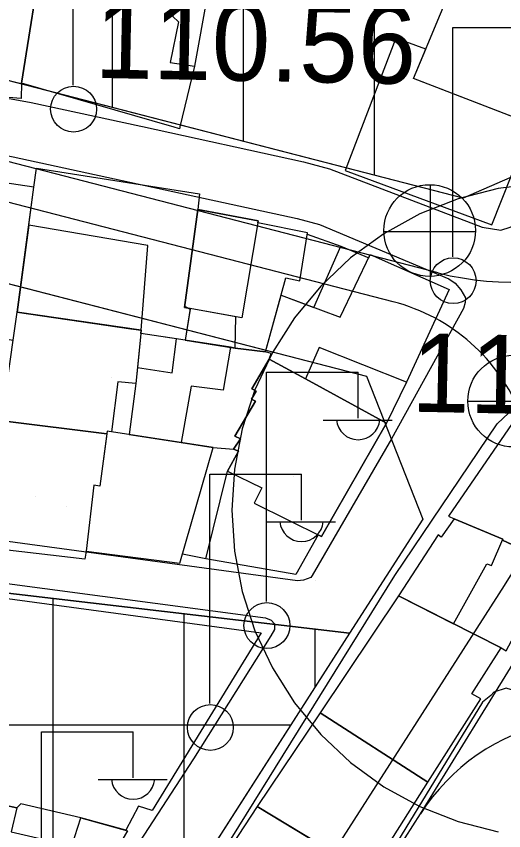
# Model space of a CAD drawing. Extents: x 417997 to 421451, y 4451742 to 4455216.
# Drawn here: x 419408.8 to 419446, y 4452992.5 to 4453054.6 of the extents above; entities that cross this region are included whole.
import ezdxf

# ---------------------------------------------------------------- set-up
doc = ezdxf.new("R2010")
doc.units = 0
for name, color, linetype in [('ADA', 7, 'Continuous'), ('ADAKENARI', 7, 'Continuous'), ('B_Mesken', 7, 'Continuous'), ('B_Teras', 7, 'Continuous'), ('Default', 7, 'Continuous'), ('KALDIRIM', 7, 'Continuous'), ('KD_KAV_25', 7, 'Continuous'), ('PL_AYA_PARK_DINLENME', 7, 'Continuous'), ('PL_K_TALI_IS_MRK', 7, 'Continuous'), ('PL_KON_MEV_350', 7, 'Continuous'), ('S_Elektrik_Diregi', 7, 'Continuous'), ('S_Rogar_Kapagi', 7, 'Continuous'), ('S_Rogar_Kapagi_Buski', 7, 'Continuous'), ('Sinir_Duvar_tek_tarafa_ait', 7, 'Continuous'), ('TR_ORTAYOGUNKONUT', 7, 'Continuous'), ('TR_PARKALANI', 7, 'Continuous'), ('TR_TALIISMERK', 7, 'Continuous'), ('Y_Kot_Noktasi', 7, 'Continuous'), ('Y_Yol_Kotu', 7, 'Continuous'), ('Yol_Sose', 7, 'Continuous')]:
    doc.layers.add(name, color=color, linetype=linetype)

# ---------------------------------------------------------------- blocks, each defined once
blk = doc.blocks.new('POINT_DISPLAY')
at = {"layer": 'Default'}
blk.add_line((0, 0), (0, 0), dxfattribs=at)

msp = doc.modelspace()

# ---------------------------------------------------------------- linework, layer by layer
at = {"layer": 'ADA'}
msp.add_line((419355.52, 4453016.764), (419434.233, 4453007.553), dxfattribs=at)
msp.add_line((419355.52, 4453016.764), (419434.233, 4453007.553), dxfattribs=at)
at = {"layer": 'ADAKENARI'}
for p, q in [((419442.899, 4453040.766), (419384.91, 4453055.74)), ((419442.899, 4453040.766), (419384.91, 4453055.74)), ((419457.346, 4453047.058), (419442.899, 4453040.766)), ((419457.346, 4453047.058), (419442.899, 4453040.766)), ((419381.159, 4453041.217), (419435.524, 4453027.178)), ((419381.159, 4453041.217), (419435.524, 4453027.178)), ((419435.524, 4453027.178), (419439.812, 4453016.259)), ((419435.524, 4453027.178), (419439.812, 4453016.259)), ((419439.812, 4453016.259), (419434.233, 4453007.553)), ((419439.812, 4453016.259), (419434.233, 4453007.553)), ((419434.233, 4453007.553), (419385.322, 4452931.225)), ((419434.233, 4453007.553), (419385.322, 4452931.225))]:
    msp.add_line(p, q, dxfattribs=at)
at = {"layer": 'B_Mesken'}
for points in [[(419420.666, 4453046.222), (419409.186, 4453049.529), (419410.842, 4453059.952), (419411.033, 4453061.438), (419421.12, 4453059.541), (419421.636, 4453062.642), (419424.233, 4453062.289), (419423.393, 4453056.331), (419421.129, 4453056.77), (419420.742, 4453054.629), (419421.174, 4453054.212), (419420.522, 4453051.125), (419422.377, 4453050.845), (419421.271, 4453046.216), (419421.265, 4453046.19), (419421.234, 4453046.059), (419420.758, 4453046.196)], [(419402.672, 4453060.235), (419410.741, 4453059.319), (419409.186, 4453049.529), (419409.149, 4453048.363), (419401.142, 4453049.015), (419401.09, 4453049.314)], [(419449.396, 4453045.919), (419439.117, 4453049.894), (419443.231, 4453059.792), (419455.025, 4453054.467), (419455.109, 4453053.862), (419451.734, 4453045.894), (419451.722, 4453045.865), (419451.414, 4453045.138), (419449.472, 4453045.889)], [(419439.117, 4453049.894), (419440.047, 4453052.132), (419437.763, 4453052.968), (419433.899, 4453042.869), (419445.103, 4453038.723), (419448.143, 4453046.403)], [(419401.551, 4453042.864), (419400.277, 4453032.838), (419400.042, 4453031.307), (419408.543, 4453029.914), (419408.843, 4453032.044), (419410.132, 4453041.595)], [(419408.843, 4453032.044), (419409.742, 4453038.702), (419410.132, 4453041.595), (419410.315, 4453043.054), (419422.759, 4453041.102), (419422.654, 4453039.904), (419421.637, 4453032.52), (419422.057, 4453032.29), (419421.686, 4453029.929), (419418.294, 4453030.428), (419418.319, 4453030.675), (419408.843, 4453032.044), (419409.742, 4453038.702)], [(419431.014, 4453038.126), (419427.219, 4453038.879), (419427.243, 4453039.021), (419422.654, 4453039.904), (419421.622, 4453032.414), (419422.064, 4453032.334), (419421.686, 4453029.929), (419425.496, 4453029.315), (419427.818, 4453029.023), (419429.358, 4453034.667), (419430.435, 4453034.442)], [(419433.569, 4453037.098), (419435.694, 4453036.204), (419435.814, 4453036.454), (419441.841, 4453033.784), (419438.568, 4453026.717), (419437.043, 4453023.586), (419430.855, 4453026.965), (419428.099, 4453028.47), (419428.249, 4453028.9), (419427.818, 4453029.023), (419429.002, 4453033.361), (419431.505, 4453032.42)], [(419408.04, 4453026.336), (419408.843, 4453032.044), (419417.525, 4453030.773), (419418.319, 4453030.675), (419417.905, 4453026.603), (419416.53, 4453026.727), (419416.062, 4453022.919), (419415.724, 4453022.972), (419415.696, 4453022.76), (419407.741, 4453023.767)], [(419417.905, 4453026.603), (419417.398, 4453022.714), (419421.36, 4453022.103), (419423.81, 4453021.726), (419425.375, 4453021.602), (419425.89, 4453022.374), (419425.461, 4453022.578), (419427.044, 4453025.271), (419426.75, 4453025.416), (419427.096, 4453026.03), (419426.775, 4453026.203), (419428.099, 4453028.47), (419428.249, 4453028.9), (419427.818, 4453029.023), (419425.496, 4453029.315), (419425.149, 4453029.371), (419421.686, 4453029.929), (419421.02, 4453030.027), (419418.294, 4453030.428), (419418.029, 4453027.821)], [(419431.821, 4453015.048), (419430.118, 4453012.031), (419423.244, 4453013.218), (419424.912, 4453019.905), (419425.751, 4453021.454), (419425.375, 4453021.602), (419425.89, 4453022.374), (419425.461, 4453022.578), (419427.044, 4453025.271), (419426.75, 4453025.416), (419427.096, 4453026.03), (419426.775, 4453026.203), (419428.099, 4453028.47), (419430.855, 4453026.965), (419437.043, 4453023.586), (419432.087, 4453014.916)], [(419407.741, 4453023.767), (419415.696, 4453022.76), (419415.172, 4453018.773), (419414.703, 4453018.843), (419414.114, 4453013.812), (419414.007, 4453013.204), (419406.563, 4453014.05), (419406.7, 4453014.834)], [(419449.452, 4453013.005), (419453.702, 4453020.945), (419447.42, 4453023.91), (419447.16, 4453023.409), (419446.642, 4453023.566), (419441.778, 4453016.491), (419442.203, 4453016.287), (419445.931, 4453014.725), (419445.895, 4453014.64)], [(419415.724, 4453022.972), (419415.172, 4453018.773), (419414.703, 4453018.843), (419414.114, 4453013.812), (419421.263, 4453012.88), (419423.81, 4453021.726)], [(419445.808, 4453006.43), (419446.187, 4453006.205), (419449.753, 4453012.867), (419445.895, 4453014.64), (419445.931, 4453014.725), (419442.203, 4453016.287), (419441.23, 4453014.872), (419441.006, 4453015.062), (419437.974, 4453010.4)], [(419407.736, 4453010.236), (419427.49, 4453007.565), (419419.151, 4452994.016), (419418.111, 4452994.347), (419417.152, 4452992.492), (419413.708, 4452993.452), (419409.131, 4452994.518), (419408.813, 4452994.207), (419406.912, 4452994.625), (419407.667, 4452997.33), (419405.031, 4452997.855), (419405.429, 4452999.7), (419405.672, 4452999.668)], [(419431.981, 4453001.461), (419440.208, 4452996.16), (419444.239, 4453002.528), (419443.566, 4453002.91), (419445.808, 4453006.43), (419437.974, 4453010.4)], [(419431.981, 4453001.461), (419427.178, 4452994.322), (419435.749, 4452989.116), (419440.208, 4452996.16)], [(419405.788, 4452993.345), (419406.106, 4452994.803), (419408.813, 4452994.207), (419408.39, 4452992.368), (419413.023, 4452991.301), (419413.708, 4452993.452), (419417.282, 4452992.456), (419410.401, 4452980.854), (419403.442, 4452982.29), (419403.523, 4452982.486), (419403.934, 4452984.794), (419404.258, 4452984.736)], [(419427.178, 4452994.322), (419422.828, 4452987.667), (419431.329, 4452982.651), (419435.468, 4452989.286)]]:
    msp.add_lwpolyline(points, close=True, dxfattribs=at)
at = {"layer": 'B_Teras'}
for points in [[(419409.742, 4453038.702), (419410.132, 4453041.595), (419410.315, 4453043.054), (419422.759, 4453041.102), (419422.654, 4453039.904), (419421.637, 4453032.52), (419422.057, 4453032.29), (419421.686, 4453029.929), (419418.294, 4453030.428), (419418.319, 4453030.675), (419418.829, 4453037.143)], [(419421.622, 4453032.414), (419422.654, 4453039.904), (419427.243, 4453039.021), (419425.996, 4453031.619)], [(419429.002, 4453033.361), (419433.512, 4453031.665), (419435.814, 4453036.454), (419441.841, 4453033.784), (419438.568, 4453026.717), (419431.914, 4453029.353), (419430.855, 4453026.965), (419428.099, 4453028.47), (419428.249, 4453028.9), (419427.818, 4453029.023)], [(419422.064, 4453032.334), (419421.686, 4453029.929), (419425.496, 4453029.315), (419425.551, 4453031.7)], [(419418.294, 4453030.428), (419418.029, 4453027.821), (419420.68, 4453027.436), (419421.02, 4453030.027)], [(419425.149, 4453029.371), (419424.567, 4453026.099), (419422.129, 4453026.41), (419421.36, 4453022.103), (419423.81, 4453021.726), (419425.375, 4453021.602), (419425.89, 4453022.374), (419425.461, 4453022.578), (419427.044, 4453025.271), (419426.75, 4453025.416), (419427.096, 4453026.03), (419426.775, 4453026.203), (419428.099, 4453028.47), (419428.249, 4453028.9), (419427.818, 4453029.023), (419425.496, 4453029.315)], [(419428.099, 4453028.47), (419426.775, 4453026.203), (419427.096, 4453026.03), (419426.75, 4453025.416), (419427.044, 4453025.271), (419425.461, 4453022.578), (419425.89, 4453022.374), (419425.375, 4453021.602), (419425.751, 4453021.454), (419424.912, 4453019.905), (419427.534, 4453018.651), (419426.953, 4453017.475), (419432.087, 4453014.916), (419437.043, 4453023.586)], [(419442.176, 4453008.27), (419444.715, 4453012.827), (419445.078, 4453012.723), (419445.931, 4453014.725), (419442.203, 4453016.287), (419441.23, 4453014.872), (419441.006, 4453015.062), (419437.974, 4453010.4)]]:
    msp.add_lwpolyline(points, close=True, dxfattribs=at)
at = {"layer": 'KALDIRIM'}
for p, q in [((419441.005, 4453035.058), (419383.409, 4453049.931)), ((419441.005, 4453035.058), (419383.409, 4453049.931)), ((419437.561, 4453032.849), (419382.659, 4453047.026)), ((419437.561, 4453032.849), (419382.659, 4453047.026)), ((419439.64, 4452993.75), (419460.258, 4453027.246)), ((419439.64, 4452993.75), (419460.258, 4453027.246)), ((419392.057, 4452926.909), (419446.065, 4453011.19)), ((419392.057, 4452926.909), (419446.065, 4453011.19)), ((419395.425, 4452924.751), (419439.64, 4452993.75)), ((419395.425, 4452924.751), (419439.64, 4452993.75))]:
    msp.add_line(p, q, dxfattribs=at)
for centre, radius, start, end in [((419446.493, 4453056.311), 21.95, 255.52117, 331.54687), ((419446.493, 4453056.311), 21.95, 255.52117, 331.54687), ((419433.97, 4453018.94), 14.365, 327.34809, 75.52117), ((419433.97, 4453018.94), 14.365, 327.34809, 75.52117), ((419453.09, 4452985.131), 15.974, 57.20227, 147.34809), ((419453.09, 4452985.131), 15.974, 57.20227, 147.34809)]:
    msp.add_arc(centre, radius, start, end, dxfattribs=at)
at = {"layer": 'KD_KAV_25'}
for p, q in [((419448.677, 4453041.883), (419445.562, 4453041.489)), ((419448.677, 4453041.883), (419445.562, 4453041.489)), ((419445.562, 4453041.489), (419442.521, 4453040.709)), ((419445.562, 4453041.489), (419442.521, 4453040.709)), ((419442.521, 4453040.709), (419439.602, 4453039.553)), ((419442.521, 4453040.709), (419439.602, 4453039.553)), ((419439.602, 4453039.553), (419436.851, 4453038.04)), ((419439.602, 4453039.553), (419436.851, 4453038.04)), ((419436.851, 4453038.04), (419434.311, 4453036.195)), ((419436.851, 4453038.04), (419434.311, 4453036.195)), ((419434.311, 4453036.195), (419432.022, 4453034.046)), ((419434.311, 4453036.195), (419432.022, 4453034.046)), ((419432.022, 4453034.046), (419430.021, 4453031.627)), ((419432.022, 4453034.046), (419430.021, 4453031.627)), ((419430.021, 4453031.627), (419428.339, 4453028.976)), ((419430.021, 4453031.627), (419428.339, 4453028.976)), ((419428.339, 4453028.976), (419427.002, 4453026.135)), ((419428.339, 4453028.976), (419427.002, 4453026.135)), ((419427.002, 4453026.135), (419426.032, 4453023.149)), ((419427.002, 4453026.135), (419426.032, 4453023.149)), ((419426.032, 4453023.149), (419425.443, 4453020.066)), ((419426.032, 4453023.149), (419425.443, 4453020.066)), ((419425.443, 4453020.066), (419425.246, 4453016.932)), ((419425.443, 4453020.066), (419425.246, 4453016.932)), ((419425.246, 4453016.932), (419425.443, 4453013.799)), ((419425.246, 4453016.932), (419425.443, 4453013.799)), ((419425.443, 4453013.799), (419426.032, 4453010.715)), ((419425.443, 4453013.799), (419426.032, 4453010.715)), ((419426.032, 4453010.715), (419427.002, 4453007.729)), ((419426.032, 4453010.715), (419427.002, 4453007.729)), ((419427.002, 4453007.729), (419428.339, 4453004.888)), ((419427.002, 4453007.729), (419428.339, 4453004.888)), ((419428.339, 4453004.888), (419430.021, 4453002.238)), ((419428.339, 4453004.888), (419430.021, 4453002.238)), ((419430.021, 4453002.238), (419432.022, 4452999.819)), ((419430.021, 4453002.238), (419432.022, 4452999.819)), ((419432.022, 4452999.819), (419434.311, 4452997.669)), ((419432.022, 4452999.819), (419434.311, 4452997.669)), ((419434.311, 4452997.669), (419436.851, 4452995.824)), ((419434.311, 4452997.669), (419436.851, 4452995.824)), ((419436.851, 4452995.824), (419439.602, 4452994.312)), ((419436.851, 4452995.824), (419439.602, 4452994.312)), ((419439.602, 4452994.312), (419442.521, 4452993.156)), ((419439.602, 4452994.312), (419442.521, 4452993.156)), ((419442.521, 4452993.156), (419445.562, 4452992.375)), ((419442.521, 4452993.156), (419445.562, 4452992.375))]:
    msp.add_line(p, q, dxfattribs=at)
at = {"layer": 'PL_AYA_PARK_DINLENME'}
msp.add_lwpolyline([(419435.524, 4453027.178), (419439.812, 4453016.259), (419434.233, 4453007.553), (419355.52, 4453016.764), (419351.123, 4453030.039), (419370.073, 4453034.551), (419381.159, 4453041.217)], close=True, dxfattribs=at)
msp.add_lwpolyline([(419435.524, 4453027.178), (419439.812, 4453016.259), (419434.233, 4453007.553), (419355.52, 4453016.764), (419351.123, 4453030.039), (419370.073, 4453034.551), (419381.159, 4453041.217)], close=True, dxfattribs=at)
at = {"layer": 'PL_K_TALI_IS_MRK'}
msp.add_lwpolyline([(419351.123, 4453030.039), (419355.52, 4453016.764), (419434.233, 4453007.553), (419385.322, 4452931.225), (419381.957, 4452925.774), (419378.777, 4452920.212), (419375.787, 4452914.546), (419372.99, 4452908.783), (419370.389, 4452902.929), (419367.986, 4452896.99), (419365.785, 4452890.974), (419363.788, 4452884.887), (419356.255, 4452860.545), (419311.592, 4452881.387), (419331.265, 4452969.872), (419325.562, 4453006.946), (419318.406, 4453048.334), (419318.411, 4453048.333), (419345.58, 4453046.776)], close=True, dxfattribs=at)
msp.add_lwpolyline([(419351.123, 4453030.039), (419355.52, 4453016.764), (419434.233, 4453007.553), (419385.322, 4452931.225), (419381.957, 4452925.774), (419378.777, 4452920.212), (419375.787, 4452914.546), (419372.99, 4452908.783), (419370.389, 4452902.929), (419367.986, 4452896.99), (419365.785, 4452890.974), (419363.788, 4452884.887), (419356.255, 4452860.545), (419311.592, 4452881.387), (419331.265, 4452969.872), (419325.562, 4453006.946), (419318.406, 4453048.334), (419318.411, 4453048.333), (419345.58, 4453046.776)], close=True, dxfattribs=at)
at = {"layer": 'PL_KON_MEV_350'}
msp.add_lwpolyline([(419521.565, 4453165.566), (419457.346, 4453047.058), (419442.899, 4453040.766), (419384.91, 4453055.74), (419380.175, 4453056.902), (419375.414, 4453057.947), (419370.628, 4453058.875), (419365.821, 4453059.686), (419360.996, 4453060.38), (419356.155, 4453060.955), (419351.302, 4453061.413), (419346.439, 4453061.751), (419319.269, 4453063.309), (419317.515, 4453063.401), (419315.761, 4453063.476), (419314.005, 4453063.533), (419312.249, 4453063.574), (419310.493, 4453063.597), (419308.737, 4453063.604), (419306.981, 4453063.593), (419305.225, 4453063.565), (419284.03, 4453063.124)], dxfattribs=at)
at = {"layer": 'S_Elektrik_Diregi'}
for p, q in [((419413.12, 4453049.393), (419413.12, 4453066.894)), ((419442.102, 4453036.291), (419442.102, 4453053.792)), ((419442.102, 4453053.792), (419449.102, 4453053.792)), ((419427.88, 4453009.962), (419427.88, 4453027.462)), ((419427.88, 4453027.462), (419434.88, 4453027.462)), ((419434.88, 4453023.962), (419434.88, 4453027.462)), ((419432.22, 4453023.822), (419437.47, 4453023.822)), ((419423.562, 4453002.182), (419423.562, 4453019.682)), ((419423.562, 4453019.682), (419430.562, 4453019.682)), ((419430.562, 4453016.182), (419430.562, 4453019.682)), ((419427.902, 4453016.042), (419433.152, 4453016.042)), ((419410.699, 4452982.512), (419410.699, 4453000.012)), ((419410.699, 4453000.012), (419417.699, 4453000.012)), ((419417.699, 4452996.512), (419417.699, 4453000.012)), ((419415.039, 4452996.372), (419420.289, 4452996.372))]:
    msp.add_line(p, q, dxfattribs=at)
for centre in [(419413.156, 4453047.558), (419442.138, 4453034.456), (419427.916, 4453008.126), (419423.598, 4453000.346)]:
    msp.add_circle(centre, 1.75, dxfattribs=at)
for centre in [(419434.881, 4453023.975), (419430.563, 4453016.195), (419417.7, 4452996.525)]:
    msp.add_arc(centre, 1.658, 184.83843, 355.14641, dxfattribs=at)
at = {"layer": 'S_Rogar_Kapagi'}
for p, q in [((419440.4, 4453034.761), (419440.4, 4453041.761)), ((419436.83, 4453038.226), (419443.83, 4453038.226))]:
    msp.add_line(p, q, dxfattribs=at)
msp.add_circle((419440.347, 4453038.29), 3.5, dxfattribs=at)
at = {"layer": 'S_Rogar_Kapagi_Buski'}
msp.add_line((419443.254, 4453025.265), (419450.254, 4453025.265), dxfattribs=at)
msp.add_circle((419446.754, 4453025.265), 3.5, dxfattribs=at)
at = {"layer": 'Sinir_Duvar_tek_tarafa_ait'}
for points in [[(419423.393, 4453056.331), (419422.377, 4453050.845)], [(419430.994, 4453037.999), (419433.569, 4453037.098)], [(419423.244, 4453013.218), (419421.463, 4453013.574)]]:
    msp.add_lwpolyline(points, dxfattribs=at)
at = {"layer": 'TR_ORTAYOGUNKONUT'}
for p, q in [((419416.12, 4453047.681), (419416.12, 4453192.359)), ((419416.12, 4453047.681), (419416.12, 4453192.359)), ((419426.12, 4453045.099), (419426.12, 4453190.726)), ((419426.12, 4453045.099), (419426.12, 4453190.726)), ((419436.12, 4453042.517), (419436.12, 4453189.092)), ((419436.12, 4453042.517), (419436.12, 4453189.092))]:
    msp.add_line(p, q, dxfattribs=at)
at = {"layer": 'TR_TALIISMERK'}
for p, q in [((419411.592, 4452972.221), (419411.592, 4453010.202)), ((419411.592, 4452972.221), (419411.592, 4453010.202)), ((419421.592, 4452987.827), (419421.592, 4453009.032)), ((419421.592, 4452987.827), (419421.592, 4453009.032)), ((419431.592, 4453003.432), (419431.592, 4453007.862)), ((419431.592, 4453003.432), (419431.592, 4453007.862)), ((419326.546, 4453000.545), (419429.742, 4453000.545)), ((419326.546, 4453000.545), (419429.742, 4453000.545))]:
    msp.add_line(p, q, dxfattribs=at)
at = {"layer": 'Yol_Sose'}
for points in [[(419393.013, 4453050.734), (419399.522, 4453049.747), (419399.626, 4453049.712), (419399.678, 4453049.52), (419399.834, 4453049.205), (419400.061, 4453049.065), (419408.385, 4453048.354), (419409.921, 4453048.073), (419418.29, 4453046.247)], [(419395.813, 4453046.462), (419408.555, 4453043.911), (419430.219, 4453039.2), (419431.929, 4453038.743), (419441.812, 4453034.591), (419442.282, 4453034.277), (419442.734, 4453033.77), (419443.081, 4453033.141), (419443.063, 4453032.792), (419442.922, 4453032.338), (419437.425, 4453022.382), (419431.369, 4453011.942), (419431.263, 4453011.803), (419430.704, 4453011.594), (419430.25, 4453011.543), (419407.156, 4453014.67), (419400.492, 4453015.361), (419389.274, 4453016.288), (419380.672, 4453016.616)], [(419418.29, 4453046.247), (419418.411, 4453046.221)], [(419418.411, 4453046.221), (419430.72, 4453043.536), (419432.692, 4453043.009), (419444.344, 4453038.556), (419445.775, 4453038.327), (419446.492, 4453038.553), (419446.877, 4453038.727), (419452.522, 4453045.263), (419453, 4453045.852)], [(419408.371, 4452965.232), (419422.396, 4452987.346), (419437.686, 4453011.951), (419445.49, 4453023.537), (419446.383, 4453024.373), (419446.994, 4453024.616), (419447.797, 4453024.632), (419447.989, 4453024.597), (419452.24, 4453022.583), (419453.478, 4453022.128), (419474.278, 4453015.271)], [(419406.919, 4453011.495), (419427.798, 4453008.721), (419428.251, 4453008.528), (419428.494, 4453008.266), (419428.493, 4453007.83), (419428.212, 4453007.342), (419422.318, 4452997.951), (419413.74, 4452984.778), (419411.039, 4452980.719), (419410.323, 4452980.371), (419364.35, 4452988.442)], [(419481.415, 4452992.709), (419449.367, 4453002.36), (419446.193, 4453003.343), (419445.25, 4453003.03), (419445.005, 4453002.787), (419444.374, 4453002.265), (419434.231, 4452985.644), (419405.436, 4452939.32)]]:
    msp.add_lwpolyline(points, dxfattribs=at)

# ---------------------------------------------------------------- block references
at = {"layer": 'TR_PARKALANI', "xscale": 0.1, "yscale": 0.10000000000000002}
for p in [(419418.323, 4453029.556), (419418.323, 4453029.556), (419416.08, 4453027.058), (419416.08, 4453027.058), (419424.984, 4453020.576), (419424.984, 4453020.576), (419429.984, 4453019.529), (419429.984, 4453019.529), (419410.212, 4453017.972), (419410.212, 4453017.972), (419412.614, 4453017.195), (419412.614, 4453017.195), (419431.645, 4453011.597), (419431.645, 4453011.597)]:
    msp.add_blockref('POINT_DISPLAY', p, dxfattribs=at)

# ---------------------------------------------------------------- texts
at = {"layer": 'Y_Kot_Noktasi'}
msp.add_text('110.56 ', height=6, rotation=358.87031, dxfattribs=at).set_placement((419414.732, 4453049.949))
at = {"layer": 'Y_Yol_Kotu'}
msp.add_text('111.61 ', height=6, rotation=358.87031, dxfattribs=at).set_placement((419438.907, 4453024.46))

doc.saveas('drawing.dxf')
